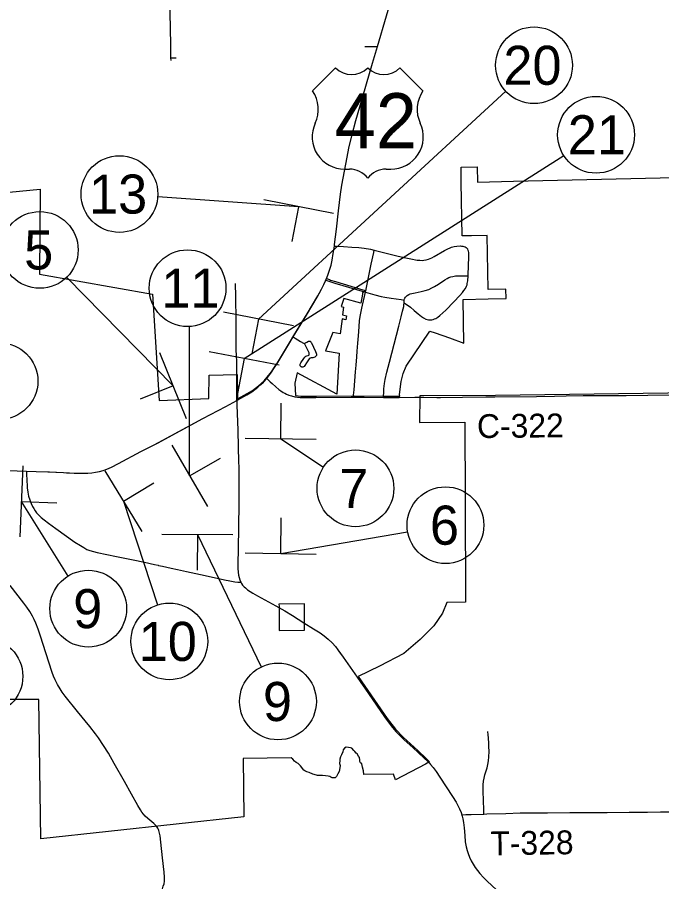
# Model space of a CAD drawing. Extents: x 40529 to 41139, y 15164 to 15584.
# Drawn here: x 40597.9 to 40644, y 15483.8 to 15545.7 of the extents above; entities that cross this region are included whole.
import ezdxf

# ---------------------------------------------------------------- set-up
doc = ezdxf.new("R2010")
doc.units = 0
for name, color, linetype in [('Default', 7, 'Continuous'), ('GM_X_Corporation', 7, 'Continuous'), ('GM_X_County_Road', 7, 'Continuous'), ('GM_X_County_Road_Text', 7, 'Continuous'), ('GM_X_State_Route', 7, 'Continuous'), ('GM_X_Township_Road', 7, 'Continuous'), ('GM_X_Township_Road_Text', 7, 'Continuous'), ('GM_X_US_Route', 7, 'Continuous'), ('GM_X_US_Shield', 7, 'Continuous'), ('SH_Data', 7, 'Continuous'), ('SH_Text', 7, 'Continuous')]:
    doc.layers.add(name, color=color, linetype=linetype)

msp = doc.modelspace()

# ---------------------------------------------------------------- linework, layer by layer
at = {"layer": 'Default'}
for p, q in [((40620.547, 15531.671), (40615.544, 15532.643)), ((40618.046, 15532.157), (40617.56, 15529.656)), ((40617.672, 15523.62), (40612.669, 15524.592)), ((40615.171, 15524.106), (40614.685, 15521.605)), ((40610.007, 15516.953), (40608.096, 15521.677)), ((40616.645, 15520.788), (40611.642, 15521.76)), ((40614.143, 15521.274), (40613.657, 15518.773)), ((40609.051, 15519.315), (40606.689, 15518.359)), ((40616.762, 15515.526), (40616.803, 15518.074)), ((40614.215, 15515.567), (40619.31, 15515.485)), ((40608.962, 15515.073), (40611.509, 15510.659)), ((40610.235, 15512.866), (40612.442, 15514.14)), ((40598.287, 15513.581), (40598.077, 15508.49)), ((40604.169, 15513.231), (40606.811, 15508.874)), ((40605.49, 15511.053), (40607.668, 15512.374)), ((40598.182, 15511.035), (40600.728, 15510.93)), ((40616.762, 15507.306), (40616.803, 15509.853)), ((40613.341, 15508.649), (40608.244, 15508.668)), ((40610.793, 15508.658), (40610.783, 15506.11)), ((40614.215, 15507.347), (40619.31, 15507.265))]:
    msp.add_line(p, q, dxfattribs=at)
at = {"layer": 'GM_X_Corporation'}
for points in [[(40588.667, 15532.351), (40599.537, 15533.4), (40599.484, 15527.32), (40607.583, 15525.878), (40608.047, 15518.269), (40611.618, 15518.42), (40611.626, 15520.083), (40613.653, 15520.127), (40613.654, 15518.581), (40613.654, 15518.364), (40613.725, 15518.402), (40614.367, 15518.763), (40614.735, 15518.988), (40614.96, 15519.15), (40615.176, 15519.324), (40615.382, 15519.508), (40615.572, 15519.686), (40615.798, 15519.933), (40616.091, 15520.313), (40616.369, 15520.737), (40616.52, 15520.973), (40617.393, 15522.409), (40617.706, 15522.922), (40618.655, 15524.48), (40619.416, 15525.763), (40619.69, 15526.253), (40619.9, 15526.67), (40620.049, 15527.003), (40620.256, 15526.928), (40620.335, 15526.899), (40620.685, 15526.785), (40622.646, 15526.209), (40622.889, 15526.14), (40622.615, 15525.985), (40622.628, 15525.886), (40622.489, 15525.245), (40621.291, 15525.579), (40621.084, 15525.008), (40621.265, 15524.963), (40621.189, 15524.396), (40621.465, 15524.328), (40621.427, 15524.044), (40621.151, 15524.112), (40621.008, 15523.054), (40620.49, 15523.133), (40619.961, 15521.815), (40620.952, 15521.664), (40620.791, 15518.727), (40617.931, 15520.257), (40617.778, 15519.498), (40617.817, 15518.632), (40618.198, 15518.579), (40619.316, 15518.575), (40622.012, 15518.591), (40624.178, 15518.584), (40625.292, 15518.578), (40625.272, 15518.691), (40625.386, 15519.627), (40625.536, 15520.193), (40625.743, 15520.733), (40627.435, 15523.245), (40627.83, 15523.106), (40628.854, 15522.746), (40629.888, 15522.383), (40629.836, 15525.515), (40631.628, 15525.555), (40632.908, 15525.585), (40632.897, 15526.256), (40631.617, 15526.227), (40631.553, 15530.096), (40630.427, 15530.071), (40629.761, 15530.056), (40629.698, 15533.896), (40629.68, 15534.99), (40630.834, 15535.017), (40630.852, 15533.922), (40633.428, 15533.98), (40645, 15534.243)], [(40648.03, 15518.837), (40632.149, 15518.628), (40626.724, 15518.589), (40626.705, 15516.699), (40629.953, 15516.725), (40629.964, 15511.146), (40629.991, 15503.814), (40628.66, 15503.8), (40628.35, 15503.026), (40627.737, 15502.108), (40626.75, 15501.14), (40625.575, 15500.133), (40623.837, 15499.234), (40622.305, 15498.489), (40624.394, 15495.465), (40624.987, 15494.706), (40625.526, 15494.144), (40626.579, 15493.18), (40627.215, 15492.596), (40627.428, 15492.379), (40627.122, 15492.199), (40624.98, 15491.076), (40624.832, 15491.483), (40622.722, 15491.452), (40622.685, 15491.717), (40622.623, 15491.983), (40622.586, 15492.112), (40622.561, 15492.23), (40622.481, 15492.304), (40622.425, 15492.384), (40622.419, 15492.507), (40622.401, 15492.674), (40622.333, 15492.785), (40622.246, 15492.939), (40622.154, 15492.983), (40622.074, 15493.1), (40622.006, 15493.192), (40621.864, 15493.347), (40621.765, 15493.384), (40621.623, 15493.408), (40621.457, 15493.415), (40621.333, 15493.341), (40621.241, 15493.242), (40621.21, 15493.094), (40621.105, 15492.871), (40621.049, 15492.723), (40621.006, 15492.569), (40621, 15492.477), (40620.975, 15492.254), (40621.012, 15492.1), (40620.988, 15491.946), (40620.938, 15491.68), (40620.852, 15491.514), (40620.759, 15491.329), (40620.667, 15491.23), (40620.549, 15491.224), (40620.438, 15491.23), (40620.34, 15491.261), (40620.272, 15491.329), (40620.154, 15491.353), (40619.975, 15491.366), (40619.759, 15491.384), (40619.611, 15491.39), (40619.488, 15491.39), (40619.389, 15491.39), (40619.315, 15491.409), (40619.056, 15491.489), (40618.797, 15491.606), (40618.63, 15491.65), (40618.494, 15491.717), (40618.408, 15491.785), (40618.173, 15492.075), (40618.013, 15492.242), (40617.871, 15492.335), (40617.754, 15492.409), (40617.618, 15492.551), (40617.513, 15492.662), (40614.064, 15492.606), (40614.123, 15488.429), (40599.576, 15486.859), (40599.428, 15496.849), (40593.604, 15496.829)]]:
    msp.add_lwpolyline(points, dxfattribs=at)
msp.add_lwpolyline([(40616.639, 15503.525), (40616.651, 15501.773), (40618.467, 15501.797), (40618.467, 15502.426), (40618.472, 15503.693), (40618.472, 15503.694), (40616.637, 15503.675)], close=True, dxfattribs=at)
at = {"layer": 'GM_X_County_Road'}
for points in [[(40615.755, 15519.838), (40616.013, 15519.602), (40616.146, 15519.484), (40616.42, 15519.236), (40616.633, 15519.061), (40616.766, 15518.95)], [(40616.766, 15518.95), (40616.937, 15518.847), (40617.06, 15518.784), (40617.182, 15518.731), (40617.351, 15518.66), (40617.524, 15518.601), (40617.771, 15518.539)], [(40617.771, 15518.539), (40617.79, 15518.534), (40617.971, 15518.503), (40618.153, 15518.486), (40618.521, 15518.478), (40619.269, 15518.481), (40621.804, 15518.496), (40621.963, 15518.498)], [(40621.963, 15518.498), (40622.737, 15518.503), (40624.126, 15518.49)], [(40624.126, 15518.49), (40624.975, 15518.482), (40625.239, 15518.484)], [(40625.239, 15518.484), (40626.375, 15518.495), (40626.669, 15518.495)], [(40626.669, 15518.495), (40627.024, 15518.495), (40627.943, 15518.492), (40628.216, 15518.489), (40629.777, 15518.5), (40631.452, 15518.529), (40631.918, 15518.533), (40632.089, 15518.534)], [(40632.089, 15518.534), (40635.071, 15518.557), (40636.375, 15518.588), (40637.214, 15518.598), (40638.425, 15518.618), (40640.566, 15518.622), (40641.495, 15518.628), (40644.605, 15518.668), (40645.628, 15518.692), (40646.463, 15518.707), (40647.954, 15518.743), (40650.095, 15518.748), (40653.17, 15518.74), (40654.005, 15518.73), (40655.772, 15518.72), (40658.661, 15518.713), (40661.268, 15518.735), (40662.402, 15518.733)], [(40598.548, 15513.205), (40598.554, 15513.015), (40598.569, 15512.536), (40598.597, 15512.156)], [(40598.597, 15512.156), (40598.608, 15511.998), (40598.638, 15511.698), (40598.707, 15511.416), (40598.801, 15511.14), (40598.894, 15510.877), (40598.978, 15510.679), (40599.067, 15510.521), (40599.17, 15510.363), (40599.279, 15510.211), (40599.432, 15510.048), (40599.611, 15509.891), (40599.826, 15509.709), (40600.122, 15509.48), (40600.652, 15509.096), (40602.025, 15508.124), (40602.415, 15507.865), (40602.657, 15507.721), (40602.88, 15507.596), (40603.084, 15507.523), (40603.352, 15507.435), (40603.625, 15507.364), (40604.999, 15507.09), (40606.188, 15506.841), (40607.006, 15506.672), (40607.724, 15506.522), (40607.977, 15506.457)], [(40607.977, 15506.457), (40607.998, 15506.451), (40608.282, 15506.39), (40608.921, 15506.251), (40609.38, 15506.155)], [(40609.38, 15506.155), (40610.014, 15506.023), (40611.019, 15505.796), (40612.648, 15505.435), (40612.731, 15505.417)], [(40612.731, 15505.417), (40613.106, 15505.338), (40613.476, 15505.273), (40613.679, 15505.248), (40613.802, 15505.243), (40613.901, 15505.239)]]:
    msp.add_lwpolyline(points, dxfattribs=at)
at = {"layer": 'GM_X_State_Route'}
for p, q in [((40607.915, 15515.201), (40607.941, 15515.215)), ((40613.755, 15512.12), (40613.761, 15510.87))]:
    msp.add_line(p, q, dxfattribs=at)
for points in [[(40607.941, 15515.215), (40611.189, 15516.965), (40612.826, 15517.845), (40613.613, 15518.27)], [(40613.613, 15518.27), (40613.624, 15517.923), (40613.678, 15516.148), (40613.717, 15514.931), (40613.749, 15513.903), (40613.75, 15513.461), (40613.754, 15512.212), (40613.755, 15512.12)], [(40602.774, 15513.05), (40602.953, 15513.05), (40603.228, 15513.077), (40603.502, 15513.12), (40603.773, 15513.181), (40604.039, 15513.256), (40604.299, 15513.351), (40604.637, 15513.5), (40605.135, 15513.75), (40606.738, 15514.608), (40607.128, 15514.796), (40607.75, 15515.112), (40607.915, 15515.201)], [(40595.517, 15513.285), (40596.631, 15513.262), (40597.893, 15513.227), (40598.548, 15513.205)], [(40598.548, 15513.205), (40599.24, 15513.183), (40600.197, 15513.143), (40601.193, 15513.099), (40601.626, 15513.08)], [(40601.626, 15513.08), (40601.973, 15513.064), (40602.506, 15513.049), (40602.774, 15513.05)], [(40613.761, 15510.87), (40613.761, 15510.842), (40613.711, 15507.619), (40613.69, 15506.593), (40613.684, 15506.235), (40613.704, 15505.954), (40613.738, 15505.746), (40613.778, 15505.574), (40613.827, 15505.409), (40613.901, 15505.239)], [(40613.901, 15505.239), (40613.955, 15505.15), (40614.032, 15505.036), (40614.138, 15504.918), (40614.232, 15504.829), (40614.389, 15504.706), (40614.562, 15504.582), (40614.771, 15504.453), (40615.094, 15504.263), (40616.405, 15503.552), (40616.587, 15503.451)], [(40616.587, 15503.451), (40617.055, 15503.189), (40617.614, 15502.854), (40618.427, 15502.344)], [(40618.427, 15502.344), (40619.114, 15501.914), (40619.581, 15501.608), (40619.883, 15501.394), (40620.17, 15501.16), (40620.438, 15500.905), (40620.683, 15500.626), (40620.853, 15500.406), (40620.957, 15500.262)], [(40620.957, 15500.262), (40621.234, 15499.877), (40622.234, 15498.446)], [(40622.234, 15498.446), (40622.354, 15498.273), (40623.041, 15497.276), (40624.202, 15495.588), (40624.531, 15495.134), (40624.761, 15494.84), (40625.004, 15494.556), (40625.26, 15494.283), (40625.594, 15493.957), (40626.214, 15493.392), (40627.044, 15492.644), (40627.308, 15492.383), (40627.412, 15492.269)], [(40627.412, 15492.269), (40627.495, 15492.178), (40627.672, 15491.963), (40627.896, 15491.667), (40628.16, 15491.284), (40629.077, 15489.879), (40629.32, 15489.484), (40629.455, 15489.24), (40629.576, 15488.991), (40629.68, 15488.733), (40629.728, 15488.581), (40629.763, 15488.469), (40629.808, 15488.29), (40629.86, 15488.017), (40629.906, 15487.649), (40629.945, 15487.089), (40629.979, 15486.645), (40630.033, 15486.275), (40630.107, 15486.009), (40630.182, 15485.804), (40630.281, 15485.541), (40630.399, 15485.286), (40630.536, 15485.04), (40630.688, 15484.803), (40630.854, 15484.576), (40631.031, 15484.358), (40631.283, 15484.081), (40631.547, 15483.816), (40633.184, 15482.292)]]:
    msp.add_lwpolyline(points, dxfattribs=at)
at = {"layer": 'GM_X_Township_Road'}
for p, q in [((40608.902, 15542.832), (40609.271, 15542.834)), ((40608.906, 15542.639), (40608.902, 15542.832)), ((40622.625, 15525.108), (40622.838, 15526.038))]:
    msp.add_line(p, q, dxfattribs=at)
for points in [[(40608.902, 15542.832), (40608.9, 15542.884), (40608.88, 15543.763), (40608.842, 15546.082), (40608.812, 15547.564), (40608.809, 15547.722)], [(40622.793, 15543.633), (40623.525, 15543.63), (40623.685, 15543.629)], [(40620.603, 15529.334), (40620.753, 15529.325), (40621.247, 15529.295), (40621.844, 15529.256), (40622.367, 15529.221), (40622.727, 15529.182), (40623.181, 15529.103), (40623.459, 15529.04)], [(40622.838, 15526.038), (40622.889, 15526.251), (40623.251, 15528.048), (40623.422, 15528.863), (40623.459, 15529.04)], [(40623.459, 15529.04), (40623.748, 15528.975), (40625.177, 15528.608), (40625.719, 15528.48)], [(40625.719, 15528.48), (40626.083, 15528.408), (40626.542, 15528.331), (40626.726, 15528.312), (40626.909, 15528.309), (40627.001, 15528.316), (40627.184, 15528.347), (40627.348, 15528.395), (40627.596, 15528.495), (40627.762, 15528.578), (40628.483, 15529.008), (40628.734, 15529.14), (40628.908, 15529.215), (40628.998, 15529.247), (40629.186, 15529.291), (40629.372, 15529.32), (40629.634, 15529.339), (40629.717, 15529.337), (40629.803, 15529.327), (40629.885, 15529.307), (40629.968, 15529.273), (40630.04, 15529.228)], [(40630.18, 15527.204), (40630.186, 15527.322), (40630.22, 15527.865), (40630.24, 15528.61), (40630.236, 15528.883), (40630.221, 15528.961), (40630.197, 15529.02), (40630.152, 15529.11), (40630.091, 15529.185), (40630.04, 15529.228)], [(40625.593, 15525.258), (40625.761, 15525.156), (40625.899, 15525.072), (40626.048, 15524.958), (40626.33, 15524.712), (40626.613, 15524.467), (40626.837, 15524.296), (40626.994, 15524.195), (40627.16, 15524.106), (40627.249, 15524.071), (40627.353, 15524.048), (40627.422, 15524.038), (40627.495, 15524.038), (40627.591, 15524.052), (40627.686, 15524.077), (40627.775, 15524.109), (40627.862, 15524.147), (40627.946, 15524.191), (40628.026, 15524.242), (40628.161, 15524.349), (40628.583, 15524.742), (40629.16, 15525.329), (40629.583, 15525.793), (40629.772, 15525.999), (40629.888, 15526.146), (40629.99, 15526.302), (40630.073, 15526.47), (40630.104, 15526.558), (40630.127, 15526.649), (40630.16, 15526.834), (40630.18, 15527.204)], [(40625.603, 15525.468), (40625.614, 15525.508), (40625.65, 15525.594), (40625.705, 15525.671), (40625.761, 15525.733), (40625.819, 15525.786), (40625.933, 15525.852), (40626.042, 15525.901), (40626.402, 15525.99), (40626.816, 15526.074), (40627.117, 15526.143), (40627.369, 15526.232), (40627.586, 15526.33), (40627.783, 15526.429), (40628.07, 15526.602), (40628.512, 15526.922), (40628.674, 15527.018), (40628.81, 15527.08), (40628.943, 15527.125), (40629.096, 15527.159), (40629.273, 15527.189), (40629.599, 15527.204), (40630.038, 15527.204), (40630.18, 15527.204)], [(40613.612, 15520.031), (40613.611, 15520.365), (40613.614, 15520.57), (40613.611, 15521.036), (40613.597, 15521.52), (40613.582, 15521.872), (40613.566, 15522.26), (40613.57, 15523.957), (40613.553, 15525.721), (40613.52, 15526.643)], [(40620.001, 15526.9), (40620.208, 15526.825), (40620.287, 15526.797), (40620.637, 15526.683), (40622.596, 15526.108), (40622.838, 15526.038)], [(40622.838, 15526.038), (40623.507, 15525.845), (40623.952, 15525.728), (40624.216, 15525.671), (40624.666, 15525.59), (40625.4, 15525.495), (40625.603, 15525.468)], [(40624.126, 15518.49), (40624.128, 15518.541), (40624.141, 15518.852), (40624.158, 15519.113), (40624.203, 15519.486), (40624.245, 15519.764), (40624.37, 15520.297), (40624.552, 15521.002), (40625.062, 15522.96), (40625.228, 15523.602), (40625.381, 15524.258), (40625.48, 15524.668), (40625.568, 15525.013), (40625.583, 15525.117), (40625.593, 15525.258)], [(40625.593, 15525.258), (40625.593, 15525.363), (40625.603, 15525.468)], [(40621.963, 15518.498), (40621.98, 15518.651), (40622.022, 15519.02), (40622.128, 15520.323), (40622.162, 15520.788), (40622.224, 15521.397), (40622.248, 15521.806), (40622.288, 15522.368), (40622.322, 15522.901), (40622.372, 15523.543), (40622.416, 15523.997), (40622.48, 15524.401), (40622.574, 15524.885), (40622.625, 15525.108)], [(40617.661, 15522.824), (40617.8, 15522.739), (40618.186, 15522.501), (40618.402, 15522.376), (40618.425, 15522.367), (40618.454, 15522.359), (40618.508, 15522.375), (40618.539, 15522.391), (40618.643, 15522.455), (40618.745, 15522.512), (40618.78, 15522.525), (40618.818, 15522.528), (40618.841, 15522.525), (40618.867, 15522.513), (40618.89, 15522.492), (40618.91, 15522.471), (40618.925, 15522.448), (40618.956, 15522.404), (40619.252, 15521.778), (40619.311, 15521.657), (40619.326, 15521.597), (40619.329, 15521.568), (40619.324, 15521.534), (40619.317, 15521.503), (40619.301, 15521.474), (40619.263, 15521.424), (40619.198, 15521.373), (40619.123, 15521.34), (40619.064, 15521.328), (40618.937, 15521.318), (40618.898, 15521.305), (40618.856, 15521.29), (40618.801, 15521.252), (40618.745, 15521.185), (40618.606, 15520.967), (40618.491, 15520.769), (40618.437, 15520.709), (40618.401, 15520.685), (40618.343, 15520.663), (40618.307, 15520.657), (40618.277, 15520.664), (40618.247, 15520.673), (40618.216, 15520.69), (40618.199, 15520.702), (40618.161, 15520.755), (40618.152, 15520.775), (40618.144, 15520.817), (40618.151, 15520.861), (40618.191, 15520.954), (40618.423, 15521.278), (40618.487, 15521.374), (40618.529, 15521.415), (40618.565, 15521.436), (40618.641, 15521.461), (40618.728, 15521.487), (40618.764, 15521.51), (40618.791, 15521.546), (40618.801, 15521.573), (40618.807, 15521.605), (40618.805, 15521.647), (40618.794, 15521.689), (40618.754, 15521.789), (40618.454, 15522.359)], [(40613.613, 15518.27), (40613.613, 15518.487), (40613.612, 15520.031)], [(40607.907, 15487.699), (40607.81, 15487.811), (40607.676, 15487.943), (40607.255, 15488.304), (40607.051, 15488.489), (40606.926, 15488.624), (40606.814, 15488.77), (40606.711, 15488.923), (40606.522, 15489.243), (40606.075, 15490.061), (40605.572, 15490.955), (40604.839, 15492.255), (40604.416, 15492.981), (40604.074, 15493.537), (40603.715, 15494.084), (40603.499, 15494.389), (40603.098, 15494.906), (40602.216, 15495.989), (40601.333, 15497.073), (40601.11, 15497.371), (40600.957, 15497.603), (40600.773, 15497.925), (40600.607, 15498.257), (40600.497, 15498.513), (40600.398, 15498.773), (40599.941, 15500.193), (40599.556, 15501.367), (40599.383, 15501.885), (40599.219, 15502.312), (40599.109, 15502.57), (40598.978, 15502.819), (40598.786, 15503.139), (40598.575, 15503.449), (40598.353, 15503.75), (40597.388, 15505.009)], [(40631.311, 15488.627), (40631.309, 15488.781), (40631.307, 15489.004), (40631.294, 15489.527), (40631.267, 15490.329), (40631.269, 15490.721), (40631.288, 15490.981), (40631.323, 15491.201), (40631.38, 15491.436), (40631.541, 15491.951), (40631.6, 15492.185), (40631.643, 15492.441), (40631.668, 15492.718), (40631.683, 15493.105), (40631.677, 15493.473), (40631.662, 15493.695), (40631.636, 15494.082), (40631.615, 15494.308), (40631.594, 15494.545)], [(40631.311, 15488.627), (40631.513, 15488.635), (40632.889, 15488.68), (40633.922, 15488.713), (40635.875, 15488.726), (40637.459, 15488.728), (40639.034, 15488.735), (40640.132, 15488.741), (40641.719, 15488.757), (40643.022, 15488.757), (40643.954, 15488.787), (40644.792, 15488.788)], [(40629.728, 15488.581), (40630.023, 15488.585), (40630.396, 15488.591), (40631.311, 15488.627)], [(40605.847, 15478.639), (40605.897, 15478.734), (40606.589, 15480.034), (40607.016, 15480.86), (40607.623, 15482.039), (40607.932, 15482.604), (40608.201, 15483.106), (40608.283, 15483.276), (40608.353, 15483.451), (40608.406, 15483.632), (40608.438, 15483.819), (40608.446, 15483.913), (40608.448, 15484.102), (40608.414, 15484.475), (40608.293, 15485.494), (40608.174, 15486.606), (40608.122, 15487.072), (40608.09, 15487.257), (40608.041, 15487.44), (40608.007, 15487.529), (40607.964, 15487.615), (40607.907, 15487.699)]]:
    msp.add_lwpolyline(points, dxfattribs=at)
at = {"layer": 'GM_X_US_Route'}
msp.add_line((40607.915, 15515.201), (40607.941, 15515.215), dxfattribs=at)
for points in [[(40620.001, 15526.9), (40620.142, 15527.257), (40620.263, 15527.611), (40620.367, 15527.97), (40620.45, 15528.335), (40620.529, 15528.795), (40620.603, 15529.334), (40620.618, 15529.442), (40620.747, 15530.553), (40620.893, 15531.848), (40621.048, 15533.048), (40621.145, 15533.691), (40621.516, 15535.706), (40621.652, 15536.343), (40621.89, 15537.34), (40622.149, 15538.331), (40622.429, 15539.316), (40623.339, 15542.447), (40623.685, 15543.629), (40624.334, 15545.845), (40625.292, 15549.091), (40625.389, 15549.42), (40625.846, 15550.883)], [(40614.571, 15518.819), (40614.693, 15518.894), (40614.918, 15519.056), (40615.134, 15519.229), (40615.34, 15519.414), (40615.529, 15519.591), (40615.755, 15519.838), (40616.047, 15520.218), (40616.325, 15520.641), (40616.476, 15520.877), (40617.348, 15522.311), (40617.661, 15522.824), (40618.609, 15524.38), (40619.37, 15525.662), (40619.643, 15526.151), (40619.853, 15526.568), (40620.001, 15526.9)], [(40613.613, 15518.27), (40613.684, 15518.309), (40614.326, 15518.669), (40614.571, 15518.819)], [(40607.941, 15515.215), (40611.189, 15516.965), (40612.826, 15517.845), (40613.613, 15518.27)], [(40602.774, 15513.05), (40602.953, 15513.05), (40603.228, 15513.077), (40603.502, 15513.12), (40603.773, 15513.181), (40604.039, 15513.256), (40604.299, 15513.351), (40604.637, 15513.5), (40605.135, 15513.75), (40606.738, 15514.608), (40607.128, 15514.796), (40607.75, 15515.112), (40607.915, 15515.201)], [(40595.517, 15513.285), (40596.631, 15513.262), (40597.893, 15513.227), (40598.548, 15513.205)], [(40598.548, 15513.205), (40599.24, 15513.183), (40600.197, 15513.143), (40601.193, 15513.099), (40601.626, 15513.08)], [(40601.626, 15513.08), (40601.973, 15513.064), (40602.506, 15513.049), (40602.774, 15513.05)]]:
    msp.add_lwpolyline(points, dxfattribs=at)
at = {"layer": 'GM_X_US_Shield'}
for p, q in [((40620.688, 15542.102), (40619.04, 15540.454)), ((40626.95, 15540.454), (40625.302, 15542.102)), ((40621.347, 15534.851), (40621.677, 15534.851)), ((40624.314, 15534.851), (40624.643, 15534.851))]:
    msp.add_line(p, q, dxfattribs=at)
for centre, radius, start, end in [((40621.842, 15543.279), 1.648, 225.573, 314.427), ((40624.149, 15543.279), 1.648, 225.573, 314.427), ((40617.15, 15539.131), 2.307, 334.54712, 35.00093), ((40628.84, 15539.131), 2.307, 144.99907, 205.45288), ((40621.322, 15537.158), 2.307, 154.83192, 270.63826), ((40624.669, 15537.158), 2.307, 269.36174, 25.16808), ((40621.677, 15533.203), 1.648, 36.8699, 90), ((40624.314, 15533.203), 1.648, 90, 143.1301)]:
    msp.add_arc(centre, radius, start, end, dxfattribs=at)
at = {"layer": 'SH_Data'}
for p, q in [((40615.171, 15524.106), (40632.882, 15540.425)), ((40614.143, 15521.274), (40637.028, 15535.833)), ((40618.046, 15532.157), (40607.953, 15532.867)), ((40609.051, 15519.315), (40601.43, 15527.092)), ((40610.235, 15512.866), (40610.235, 15523.568)), ((40616.762, 15515.526), (40619.824, 15513.491)), ((40598.182, 15511.035), (40601.522, 15505.682)), ((40605.49, 15511.053), (40607.927, 15503.616)), ((40610.793, 15508.658), (40615.37, 15499.173)), ((40616.762, 15507.306), (40625.85, 15508.866))]:
    msp.add_line(p, q, dxfattribs=at)
msp.add_lwpolyline([(40597.893, 15513.227), (40598.548, 15513.205), (40599.24, 15513.183), (40600.087, 15513.148), (40601.193, 15513.099), (40601.41, 15513.089), (40601.626, 15513.08), (40601.973, 15513.064), (40602.506, 15513.049), (40602.774, 15513.05), (40602.953, 15513.05), (40603.228, 15513.077), (40603.502, 15513.12), (40603.773, 15513.181), (40604.039, 15513.256), (40604.299, 15513.351), (40604.637, 15513.5), (40605.135, 15513.75), (40606.738, 15514.608), (40607.128, 15514.796), (40607.75, 15515.112), (40611.189, 15516.965), (40612.826, 15517.845), (40613.613, 15518.27), (40613.624, 15517.923), (40613.678, 15516.148), (40613.717, 15514.931), (40613.749, 15513.903), (40613.75, 15513.461), (40613.754, 15512.212), (40613.755, 15512.12), (40613.761, 15510.87), (40613.761, 15510.842), (40613.711, 15507.619), (40613.69, 15506.593), (40613.684, 15506.235), (40613.704, 15505.954), (40613.738, 15505.746), (40613.778, 15505.574), (40613.827, 15505.409), (40613.901, 15505.239), (40613.928, 15505.194), (40613.955, 15505.15), (40614.032, 15505.036), (40614.138, 15504.918), (40614.232, 15504.829), (40614.389, 15504.706), (40614.562, 15504.582), (40614.771, 15504.453), (40615.094, 15504.263), (40616.405, 15503.552), (40617.055, 15503.189), (40617.614, 15502.854), (40618.427, 15502.344), (40619.114, 15501.914), (40619.581, 15501.608), (40619.883, 15501.394), (40620.17, 15501.16), (40620.438, 15500.905), (40620.683, 15500.626), (40620.853, 15500.406), (40621.234, 15499.877), (40622.234, 15498.446), (40623.041, 15497.276), (40624.202, 15495.588), (40624.531, 15495.134), (40624.761, 15494.84), (40625.004, 15494.556), (40625.26, 15494.283), (40625.594, 15493.957), (40626.214, 15493.392), (40627.044, 15492.644), (40627.308, 15492.383), (40627.412, 15492.269), (40627.495, 15492.178), (40627.672, 15491.963), (40627.896, 15491.667), (40628.16, 15491.284), (40629.077, 15489.879), (40629.32, 15489.484), (40629.455, 15489.24), (40629.576, 15488.991), (40629.68, 15488.733), (40629.763, 15488.469), (40629.808, 15488.29), (40629.86, 15488.017), (40629.906, 15487.649), (40629.945, 15487.089), (40629.979, 15486.645), (40630.033, 15486.275), (40630.107, 15486.009), (40630.182, 15485.804), (40630.281, 15485.541), (40630.399, 15485.286), (40630.536, 15485.04), (40630.688, 15484.803), (40630.854, 15484.576), (40631.031, 15484.358), (40631.283, 15484.081), (40631.547, 15483.816), (40633.184, 15482.292)], dxfattribs=at)
at = {"layer": 'SH_Text'}
for centre in [(40634.904, 15542.289), (40639.348, 15537.309), (40605.209, 15533.06), (40599.505, 15529.056), (40610.09, 15526.314), (40596.618, 15519.658), (40622.115, 15511.969), (40628.56, 15509.331), (40602.977, 15503.349), (40608.783, 15501.003), (40595.539, 15498.499), (40616.565, 15496.696)]:
    msp.add_circle(centre, 2.75, dxfattribs=at)

# ---------------------------------------------------------------- texts
at = {"layer": 'GM_X_County_Road_Text'}
msp.add_text('C-322', height=1.7063, rotation=0.54928, dxfattribs=at).set_placement((40630.828, 15515.572))
at = {"layer": 'GM_X_Township_Road_Text'}
msp.add_text('T-328', height=1.7063, rotation=0.82338, dxfattribs=at).set_placement((40631.787, 15485.67))
at = {"layer": 'GM_X_US_Shield'}
msp.add_text('42', height=3.9551, dxfattribs=at).set_placement((40620.632, 15536.334))
at = {"layer": 'SH_Text'}
for s, p in [('20', (40632.711, 15540.889)), ('21', (40637.324, 15535.909)), ('13', (40603.033, 15531.66)), ('5', (40598.386, 15527.656)), ('11', (40608.21, 15524.914)), ('7', (40620.95, 15510.569)), ('6', (40627.45, 15507.931)), ('9', (40601.899, 15501.949)), ('10', (40606.59, 15499.603)), ('9', (40615.487, 15495.296))]:
    msp.add_text(s, height=2.8, dxfattribs=at).set_placement(p)

doc.saveas('drawing.dxf')
